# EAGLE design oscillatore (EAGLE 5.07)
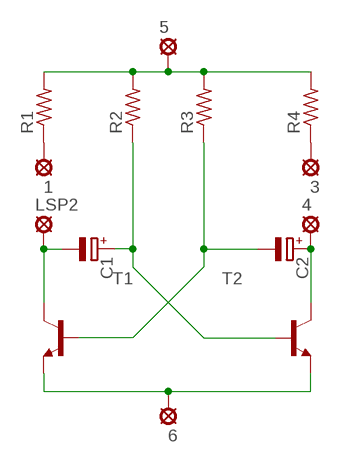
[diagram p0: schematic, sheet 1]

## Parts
1  MCS08  [MCS08]
3  MCS08  [MCS08]
4  MCS08  [MCS08]
5  MCS08  [MCS08]
6  MCS08  [MCS08]
C1  CPOL-EUE2-5  [E2-5]
C2  CPOL-EUE2-5  [E2-5]
LSP2  MCS08  [MCS08]
R1  R-US_0207/2V  [0207/2V]
R2  R-US_0207/2V  [0207/2V]
R3  R-US_0207/2V  [0207/2V]
R4  R-US_0207/2V  [0207/2V]
T1  BC337-NPN-TO92-EBC  [TO92-EBC]
T2  BC337-NPN-TO92-EBC  [TO92-EBC]

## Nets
N$1: C1.+ R2.1 T2.B
N$2: C2.- R3.1 T1.B
N$3: 4.MP C2.+ T2.C
N$4: C1.- LSP2.MP T1.C
N$5: 5.MP R1.2 R2.2 R3.2 R4.2
N$6: 6.MP T1.E T2.E
N$7: 1.MP R1.1
N$8: 3.MP R4.1

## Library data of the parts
1 3-6 LSP2 = solpad:MCS08: SOLDER PAD
C1 C2 = resistor:CPOL-EU: POLARIZED CAPACITOR, European symbol
R1-R4 = resistor:R-US_: RESISTOR, American symbol
T1 T2 = transistor:*-NPN-: NPN Transistror BF959 corrected 2008.03.06

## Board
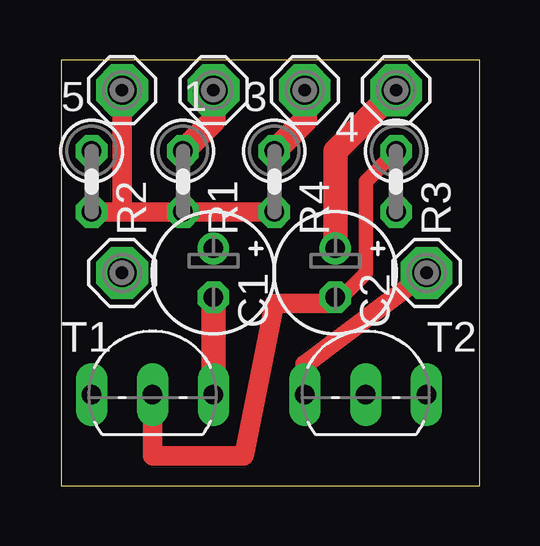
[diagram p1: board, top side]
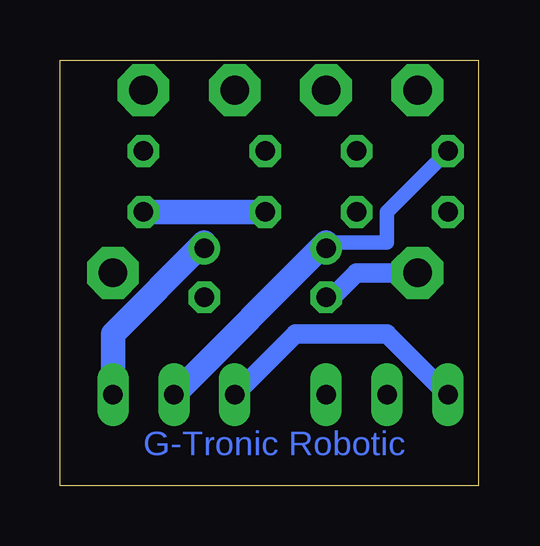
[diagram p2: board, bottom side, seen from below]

Size 17.45 x 17.77 mm. Coordinates in mm from the lower left corner, seen from the top.
Outline: 0,0 17.45,0 17.45,17.77 0,17.77 0,0
Copper layers (1*16): Top 0.035mm / dielectric 1.5mm / Bottom 0.035mm
Design rules "default": minimum track width 10mil, minimum drill 24mil, track to track 8mil, track to pad 8mil, pad to pad 8mil, via to via 8mil, smd to smd 8mil, copper to edge 40mil, drill to drill 8mil, minimum pad ring 10mil, minimum via ring 8mil, stop-mask expansion 4mil, vias tented up to drill 0mil, thermal gap 10mil

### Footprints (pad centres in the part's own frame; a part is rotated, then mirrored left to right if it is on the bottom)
MCS08 = drill 1.194 pad 2.159 octagon: MP 0,0
E2-5 = drill 0.813 pad 1.27 round: + -1.016,0 | drill 0.813 pad 1.27 octagon: - 1.016,0
0207/2V = drill 0.813 octagon: 1 -1.27,0; 2 1.27,0
TO92-EBC = drill 0.813 long: B 0,-1.27; C 2.54,-1.27; E -2.54,-1.27

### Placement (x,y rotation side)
1  6.35,16.51 0 top
3  10.16,16.51 0 top
4  13.97,16.51 0 top
5  2.54,16.51 0 top
6  15.24,8.89 0 top
C1  6.35,8.89 270 top
C2  11.43,8.89 270 top
LSP2  2.54,8.89 0 top
R1  5.08,12.7 270 top
R2  1.27,12.7 270 top
R3  13.97,12.7 270 top
R4  8.89,12.7 270 top
T1  3.81,5.08 0 top
T2  12.7,5.08 0 top

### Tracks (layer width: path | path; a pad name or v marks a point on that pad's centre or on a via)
N$1
  Bottom 0.254: C1.+ 6.35,10.16
  Bottom 0.61: R2.1 3.81,11.43 3.81,10.16 6.35,10.16
  Bottom 1.016: 6.35,10.16 T2.B
N$2
  Top 0.254: C2.- 11.43,7.62
  Top 0.61: R3.1 12.7,12.7 12.7,8.89 11.43,7.62
  Top 0.813: T1.B 3.81,1.27 7.62,1.27 8.89,7.62 11.43,7.62
N$3
  Top 1.016: 4.MP 11.43,13.97 C2.+
  Bottom 0.254: 11.43,10.16 C2.+
  Bottom 1.016: T2.C 15.24,6.35 11.43,10.16
N$4
  Top 1.016: T1.C C1.-
  Bottom 0.254: C1.- 6.35,7.62
  Bottom 0.813: 6.35,7.62 5.08,8.89 LSP2.MP
N$5
  Top 0.813: 2.54,11.43 R1.2 R4.2 | R2.2 2.54,11.43 | 2.54,11.43 5.MP
  Bottom 1.016: R4.2 R3.2
N$6
  Top 0.813: T2.E 10.16,5.08 6.MP
  Bottom 0.813: T1.E 3.81,6.35 7.62,6.35 T2.E
N$7
  Top 1.016: R1.1 6.35,15.24 1.MP
N$8
  Top 1.016: R4.1 10.16,15.24 3.MP

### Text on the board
Bottom: G-Tronic Robotic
